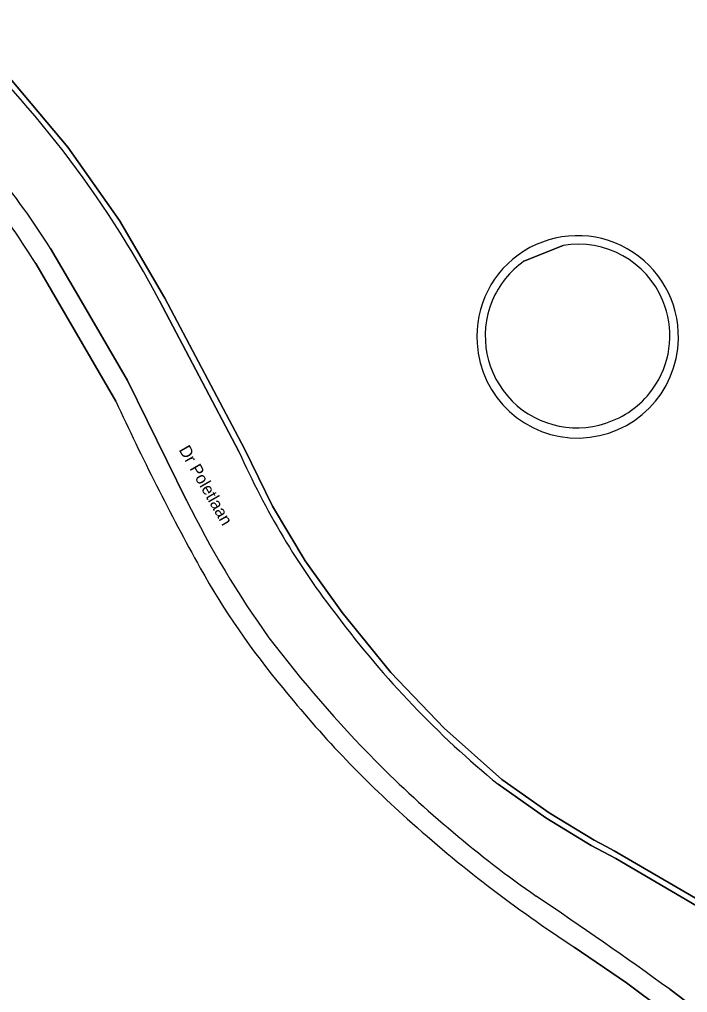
# Model space of a CAD drawing. Extents: x 158132 to 159664, y 385256 to 387218.
# Drawn here: x 159443.6 to 159498.9, y 385692.7 to 385773.3 of the extents above; entities that cross this region are included whole.
import ezdxf

# ---------------------------------------------------------------- set-up
doc = ezdxf.new("R2010")
doc.units = 0
for name, color, linetype in [('IMGEO_Berm_groen', 7, 'Continuous'), ('IMGEO_Fietspad_open', 7, 'Continuous'), ('IMGEO_Gemengd_bos', 7, 'Continuous'), ('IMGEO_Loofbos', 7, 'Continuous'), ('IMGEO_Meer_plas_ven_vijver', 7, 'Continuous'), ('IMGEO_Oever', 7, 'Continuous'), ('IMGEO_Openbare_ruimte_label', 7, 'Continuous'), ('IMGEO_Rijbaan_lokaal_gesloten', 7, 'Continuous')]:
    doc.layers.add(name, color=color, linetype=linetype)

msp = doc.modelspace()

# ---------------------------------------------------------------- linework, layer by layer
at = {"layer": 'IMGEO_Berm_groen'}
for points in [[(159483.252, 385709.974), (159487.215, 385707.187), (159490.966, 385704.917), (159493.002, 385703.831), (159499.691, 385699.925), (159505.344, 385697.255), (159505.357, 385697.249), (159505.658, 385697.659), (159499.923, 385700.368), (159492.859, 385704.474), (159492.209, 385704.821), (159491.213, 385705.352), (159487.489, 385707.606), (159483.555, 385710.372), (159478.786, 385714.619), (159474.372, 385719.233), (159470.341, 385724.187), (159467.27, 385728.476), (159464.562, 385733.003), (159462.235, 385737.737), (159455.642, 385750.234), (159451.893, 385756.647), (159447.611, 385762.718), (159442.828, 385768.402)], [(159455.2, 385750), (159461.785, 385737.519)]]:
    msp.add_lwpolyline(points, dxfattribs=at)
for centre, radius, start, end in [((159378.59, 385709.491), 86.66, 27.8686, 47.41228), ((159520.905, 385763.634), 64.631, 203.83246, 217.9553), ((159534.131, 385771.975), 80.205, 216.84259, 230.62743)]:
    msp.add_arc(centre, radius, start, end, dxfattribs=at)
at = {"layer": 'IMGEO_Fietspad_open'}
for points in [[(159457.446, 385733.462), (159452.553, 385743.407), (159448.707, 385750), (159446.172, 385754.345)], [(159444.956, 385753.086), (159446.749, 385750), (159451.578, 385741.691)], [(159489.561, 385696.503), (159493.882, 385693.526), (159500, 385688.965), (159500.873, 385688.314), (159501.64, 385689.373), (159501.863, 385689.681), (159500, 385691.091), (159497.476, 385693.001)]]:
    msp.add_lwpolyline(points, dxfattribs=at)
for centre, radius, start, end in [((159385.951, 385716.045), 71.369, 32.45631, 45.27222), ((159388.257, 385717.774), 66.796, 31.91471, 45.78328), ((159650.257, 385833.579), 218.899, 204.82038, 208.87258), ((159532.529, 385770.831), 83.868, 206.45999, 215.51502), ((159516.72, 385760.631), 66.74, 209.38745, 219.74664), ((159548.461, 385786.089), 105.747, 217.22924, 224.56496), ((159537.597, 385776.321), 92.833, 218.95361, 228.20506), ((159542.993, 385781.511), 98.641, 224.89961, 234.99031), ((159550.485, 385790.28), 111.83, 228.04835, 236.9892), ((159248.699, 385347.822), 425.486, 54.21902, 56.03687)]:
    msp.add_arc(centre, radius, start, end, dxfattribs=at)
at = {"layer": 'IMGEO_Gemengd_bos'}
for points in [[(159451.578, 385741.691), (159446.749, 385750), (159444.956, 385753.086)], [(159504.003, 385686.745), (159504.4, 385687.141), (159503.813, 385687.966), (159503.905, 385688.135), (159501.863, 385689.681), (159501.64, 385689.373), (159500.873, 385688.314), (159500, 385688.965), (159493.882, 385693.526), (159489.561, 385696.503)]]:
    msp.add_lwpolyline(points, dxfattribs=at)
for centre, radius, start, end in [((159388.257, 385717.774), 66.796, 31.91471, 45.78328), ((159650.257, 385833.579), 218.899, 204.82038, 208.87258), ((159516.72, 385760.631), 66.74, 209.38745, 219.74664), ((159537.597, 385776.321), 92.833, 218.95361, 228.20506), ((159550.485, 385790.28), 111.83, 228.04835, 236.9892)]:
    msp.add_arc(centre, radius, start, end, dxfattribs=at)
at = {"layer": 'IMGEO_Loofbos'}
msp.add_lwpolyline([(159442.828, 385768.402), (159447.611, 385762.718), (159451.893, 385756.647), (159455.642, 385750.234), (159462.235, 385737.737), (159464.562, 385733.003), (159467.27, 385728.476), (159470.341, 385724.187), (159474.372, 385719.233), (159478.786, 385714.619), (159483.555, 385710.372), (159487.489, 385707.606), (159491.213, 385705.352), (159492.209, 385704.821), (159492.859, 385704.474), (159499.923, 385700.368), (159505.658, 385697.659), (159513.523, 385708.39), (159519.49, 385704.024), (159530.672, 385721.983), (159533.675, 385726.593), (159537.431, 385731.949)], dxfattribs=at)
for centre, radius, start, end in [((159489.831, 385747.047), 8.349, 358.71122, 183.8788), ((159489.832, 385746.986), 8.347, 183.46279, 359.12723)]:
    msp.add_arc(centre, radius, start, end, dxfattribs=at)
at = {"layer": 'IMGEO_Meer_plas_ven_vijver'}
msp.add_lwpolyline([(159488.633, 385754.572), (159485.391, 385753.286)], dxfattribs=at)
for centre, radius, start, end in [((159489.907, 385747.11), 7.57, 22.44177, 99.68694), ((159489.793, 385747.074), 7.614, 125.32133, 157.39734), ((159489.778, 385747.085), 7.596, 157.43313, 292.7514), ((159489.915, 385747.109), 7.562, 327.91223, 22.47263), ((159489.911, 385747.103), 7.563, 291.7739, 327.9684)]:
    msp.add_arc(centre, radius, start, end, dxfattribs=at)
at = {"layer": 'IMGEO_Oever'}
msp.add_lwpolyline([(159485.391, 385753.286), (159488.633, 385754.572)], dxfattribs=at)
for centre, radius, start, end in [((159489.831, 385747.047), 8.349, 358.71122, 183.8788), ((159489.907, 385747.11), 7.57, 22.44177, 99.68694), ((159489.793, 385747.074), 7.614, 125.32133, 157.39734), ((159489.778, 385747.085), 7.596, 157.43313, 292.7514), ((159489.915, 385747.109), 7.562, 327.91223, 22.47263), ((159489.832, 385746.986), 8.347, 183.46279, 359.12723), ((159489.911, 385747.103), 7.563, 291.7739, 327.9684)]:
    msp.add_arc(centre, radius, start, end, dxfattribs=at)
at = {"layer": 'IMGEO_Rijbaan_lokaal_gesloten'}
for points in [[(159446.172, 385754.345), (159448.707, 385750), (159452.553, 385743.407), (159457.446, 385733.462)], [(159461.785, 385737.519), (159455.2, 385750)], [(159497.476, 385693.001), (159500, 385691.091), (159501.863, 385689.681), (159506.724, 385696.603), (159505.357, 385697.249), (159505.344, 385697.255), (159499.691, 385699.925), (159493.002, 385703.831), (159490.966, 385704.917), (159487.215, 385707.187), (159483.252, 385709.974)]]:
    msp.add_lwpolyline(points, dxfattribs=at)
for centre, radius, start, end in [((159378.59, 385709.491), 86.66, 27.8686, 47.41228), ((159385.951, 385716.045), 71.369, 32.45631, 45.27222), ((159520.905, 385763.634), 64.631, 203.83246, 217.9553), ((159532.529, 385770.831), 83.868, 206.45999, 215.51502), ((159534.131, 385771.975), 80.205, 216.84259, 230.62743), ((159548.461, 385786.089), 105.747, 217.22924, 224.56496), ((159542.993, 385781.511), 98.641, 224.89961, 234.99031), ((159248.699, 385347.822), 425.486, 54.21902, 56.03687)]:
    msp.add_arc(centre, radius, start, end, dxfattribs=at)

# ---------------------------------------------------------------- texts
at = {"layer": 'IMGEO_Openbare_ruimte_label'}
msp.add_text('Dr Poletlaan', height=1, rotation=299.95108, dxfattribs=at).set_placement((159456.772, 385737.673))

doc.saveas('drawing.dxf')
